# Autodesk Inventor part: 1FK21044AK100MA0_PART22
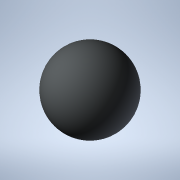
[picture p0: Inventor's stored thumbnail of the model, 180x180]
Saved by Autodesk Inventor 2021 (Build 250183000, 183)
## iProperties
Created: 2025-04
Part Number: 1FK21044AK100MA0_PART22
Material: Generic
Catalog Web Link: www.3dfindit.com
Description: -Servo synchronous motor
Document SubType Name: Modeling
Designer: psAdmin
Mass: 0.137258 g
Surface Area: 1.2868 cm^2
Volume: 0.137258 cm^3
Density: 1 g/cm^3
Appearance: PSOLRGB-212-217-219
Category: PARTsolutions
Title: 1FK21044AK100MA0_PART22
Author: Cadenas PARTsolutions
Comments: Servo synchronous motor
Sending System: PARTsolutions
Preprocessor: ST-DEVELOPER v19.3
PSOL_IDENT_0: {$CADENAS_DATA/23d-libs/siemens_ag/_cat_/5e/d8/1fk21044ak100ma0.prj},216 {VTYP=3D},{NB=1FK21044AK100
PSOL_IDENT_1: MA0_PART22},{LINA=1FK21044AK100MA0_PART22},{NN=1FK21044AK100MA0_PART22},{NOPRJ=TRUE},{DATE=19.08.202
PSOL_IDENT_2: 5 14:00:41},{GEOMDATE=30.07.2025 02:00:53},{VERSION=},{LINEID=10},{WBVAR=},{WBNUMERIC=}  {NB=1FK2104
PSOL_IDENT_3: 4AK100MA0_PART22},{LINA=1FK21044AK100MA0_PART22},{KT=DUMMY},{PREVIEW=../../../_pool_/cb/72/p_d211_xx
PSOL_IDENT_4: _00434j.png},{DESCSHORT=SIMOTICS S-1FK2 HD, SINAMICS S210 3AC 400V-480V, 0.95 Nm, 6000 rpm},{DESCLON
PSOL_IDENT_5: G=SIMOTICS S-1FK2 HD servo motor M0=1.27 Nm; PN = 0.6 kW at nN=6000 rpm (380-480 V); PN = 0.4 kW at
PSOL_IDENT_6: nN=3000 rpm (200-240 V); with holding brake; degree of protection IP64; cylindrical shaft D19x40mm;
PSOL_IDENT_7: absolute encoder 22-bit + 12-bit multiturn (encoder AM22DQC); with OCC interface; plug size M17, rot
PSOL_IDENT_8: atable; SIMOTICS S-1FK2 servomotorfor a wide range of uses in industrial environments. SIMOTICS S‑1F
PSOL_IDENT_9: K2 servomotors are compact synchronous motors with a high dynamic performance that set themselves ap
PSOL_IDENT_10: art as a result of their high power density, degree of protection and overload capability. The motor
PSOL_IDENT_11: s are available in two variants: as High Dynamic variant (highest dynamic performance as a result of
PSOL_IDENT_12: the low intrinsic moment of inertia for applications demanding a high dynamic performance with low
PSOL_IDENT_13: moved masses) - and as Compact variant (precise and stable closed-loop control for medium up to larg
PSOL_IDENT_14: e moved masses as a result of a medium intrinsic moment of inertia). SIMOTICSS‑1FK2 servomotors full
PSOL_IDENT_15: y exploit their strengths in a system with the SINAMICSS210 frequency converter and simple connectio
PSOL_IDENT_16: n using the one cable connection (OCC). Advantages include the short control and positioning times,
PSOL_IDENT_17: fast and precise correction of disturbing quantities as well as stable control with a high dynamic p
PSOL_IDENT_18: erformance. The servo motors can be configured to address a wide range of requirements. For example
PSOL_IDENT_19: with and without holding brake, IP64 or IP65 degree of protection, singleturn or multiturn absolute
PSOL_IDENT_20: encoders - to name just a few. Further, the servomotors are available in different shaft heights ext
PSOL_IDENT_21: ending from 20 to 100. A shaft sealing ring is available to achieve an IP65 degree of protection and
PSOL_IDENT_22: for subsequent mounting at the motor or as spare part. SIMOTICS - the optimum motor for each and ev
PSOL_IDENT_23: ery motion control application.},{INTNO=804766910005},{SUPPLIERALTNO=1FK2104-4AK10-0MA0},{MANUID=1FK
PSOL_IDENT_24: 21044AK100MA0},{MANUNAME=Siemens},{MANUTYPEDESC=Synchronous motor 1FK2-HD 1,27 Nm},{AAU732=SIMOTICS}
PSOL_IDENT_25: ,{AAO057=S-1FK2},{AAU734=SIMOTICS S-1FK2 HD servo motor M0=1.27 Nm; PN = 0.6 kW at nN=6000 rpm (380-
PSOL_IDENT_26: 480 V); PN = 0.4 kW at nN=3000 rpm (200-240 V); with holding brake; degree of protection IP64; cylin
PSOL_IDENT_27: drical shaft D19x40mm; absolute encoder 22-bit + 12-bit multiturn (encoder AM22DQC); with OCC interf
PSOL_IDENT_28: ace; plug size M17, rotatable;},{AAW338=Synchronous motor 1FK2-HD 1,27 Nm},{AAO742=SIMOTICS},{AAO663=
PSOL_IDENT_29: 4042948691076},{NOCUPEROU=1},{PRICEQUANTITY=1},{QUANTITYMIN=1},{QUANTITYINT=1},{CTN=85015100},{COO=D
PSOL_IDENT_30: E},{AAO676=1FK2104-4AK10-0MA0},{AAO677=Siemens AG},{ORDERUNIT=C62},{CONTENTUNIT=C62}
NB: 1FK21044AK100MA0_PART22
NT: Servo synchronous motor
NBSYN: $MANUID._PART22
LINA: 1FK21044AK100MA0_PART22
CATALOG: SIEMENS
PREVIEW: ../../../_pool_/cb/72/p_d211_xx_00434j.png
DESCSHORT: SIMOTICS S-1FK2 HD, SINAMICS S210 3AC 400V-480V, 0.95 Nm, 6000 rpm
DESCLONG: SIMOTICS S-1FK2 HD servo motor M0=1.27 Nm; PN = 0.6 kW at nN=6000 rpm (380-480 V); PN = 0.4 kW at nN=3000 rpm (200-240 V); with holding brake; degree of protect
INTNO: 804766910005
SUPPLIERALTNO: 1FK2104-4AK10-0MA0
MANUID: 1FK21044AK100MA0
MANUNAME: Siemens
MANUTYPEDESC: Synchronous motor 1FK2-HD 1,27 Nm
AAU732: SIMOTICS
AAO057: S-1FK2
AAU734: SIMOTICS S-1FK2 HD servo motor M0=1.27 Nm; PN = 0.6 kW at nN=6000 rpm (380-480 V); PN = 0.4 kW at nN=3000 rpm (200-240 V); with holding brake; degree of protect
AAW338: Synchronous motor 1FK2-HD 1,27 Nm
AAO742: SIMOTICS
AAO663: 4042948691076.0
NOCUPEROU: 1
PRICEQUANTITY: 1
QUANTITYMIN: 1
QUANTITYINT: 1
CTN: 85015100
COO: DE
ARTICLENO: 1FK21044AK100MA0_PART22
BOMINFO: 1FK21044AK100MA0_PART22
CREATOR: CADENAS GmbH
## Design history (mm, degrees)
feature "2025_04_17_15_35_41_0968"
body "Solid1"
